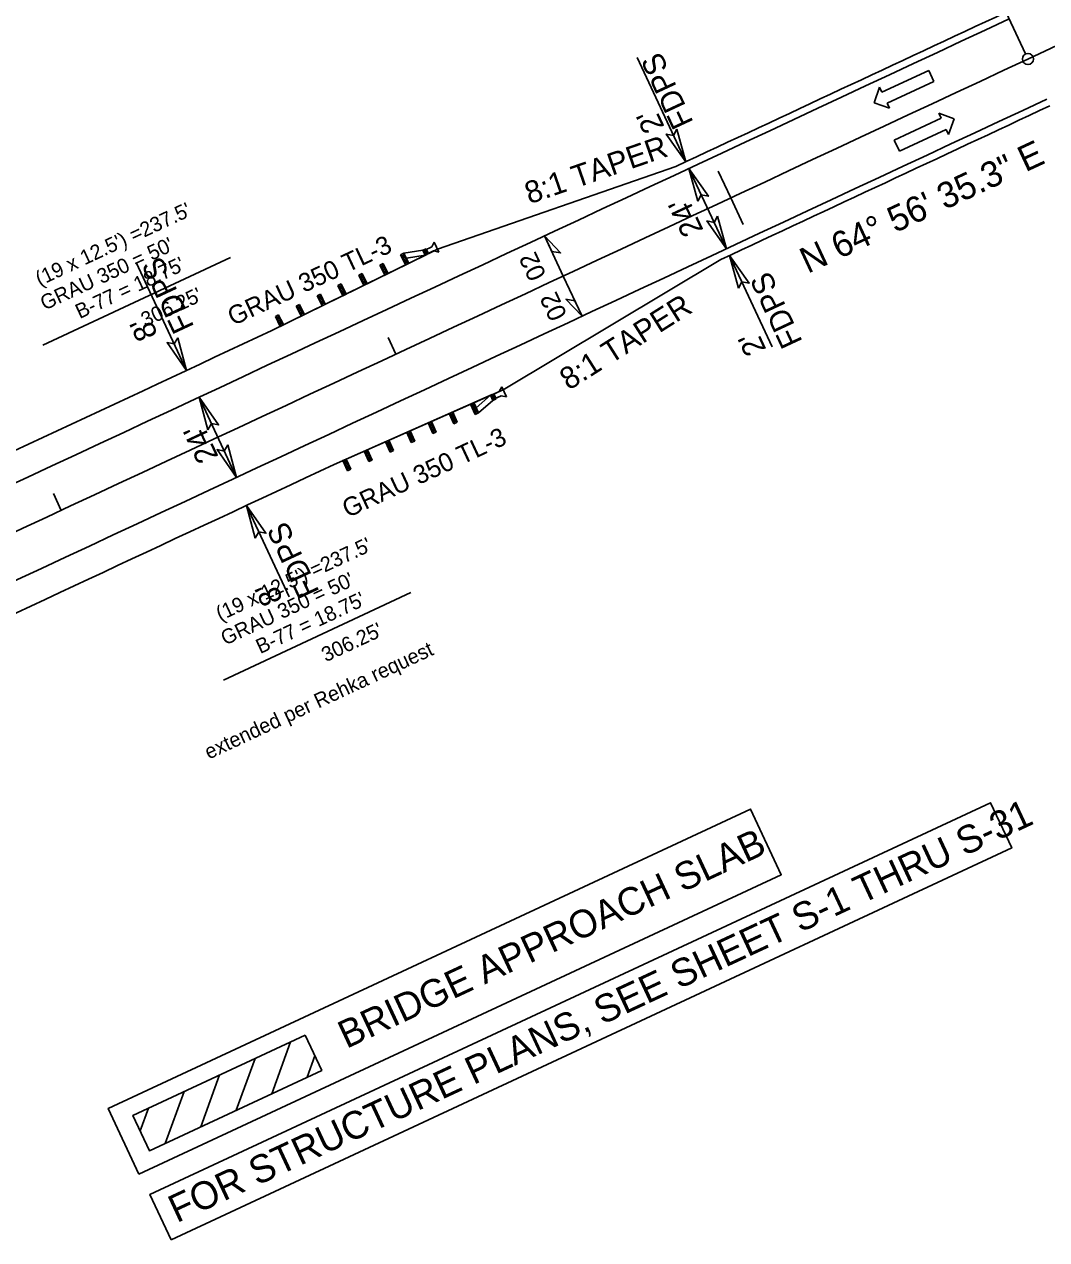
# Model space of a CAD drawing. Extents: x 2320644 to 2322941, y 921672 to 923041.
# Drawn here: x 2321947.4 to 2322224.1, y 922135.5 to 922464.6 of the extents above; entities that cross this region are included whole.
import ezdxf

# ---------------------------------------------------------------- set-up
doc = ezdxf.new("R2010")
doc.units = 0
for name, color, linetype in [('Matchline', 7, 'Continuous'), ('Matchline Text', 7, 'Continuous'), ('Prop Approach Slab', 7, 'Continuous'), ('Prop Conc Shoulder Berm Gutter', 7, 'Continuous'), ('Prop Dimension', 7, 'Continuous'), ('Prop EOT', 7, 'Continuous'), ('Prop Guardrail', 7, 'Continuous'), ('Prop Horizontal Alignment', 7, 'Continuous'), ('Prop Horizontal Alignment Station Label', 7, 'Continuous'), ('Prop Horizontal Alignment Tick Small', 7, 'Continuous'), ('Prop Lane Arrow CELL', 7, 'Continuous'), ('Prop North Arrow NAD83 for Plan Sheets CELL', 7, 'Continuous'), ('Prop Superelevation  Arrow CELL', 7, 'Continuous'), ('Sheet Sticker Exception Certification CELL', 7, 'Continuous'), ('Skimmer Basin Both CELL', 7, 'Continuous')]:
    doc.layers.add(name, color=color, linetype=linetype)

msp = doc.modelspace()

# ---------------------------------------------------------------- linework, layer by layer
at = {"layer": 'Matchline'}
msp.add_line((2322219.06, 922455.24), (2322939.2, 922791.92), dxfattribs=at)
msp.add_arc((2152812.15, 1284810.45), 400000, 294.9912984, 295.0568478, dxfattribs=at)
at = {"layer": 'Prop Approach Slab'}
for radius in [399988, 400012]:
    msp.add_arc((2152812.15, 1284810.45), radius, 294.9912984, 295.0568478, dxfattribs=at)
at = {"layer": 'Prop Conc Shoulder Berm Gutter'}
for p, q in [((2322059.26, 922403.79), (2322123.77, 922426.16)), ((2322014.38, 922381.69), (2322059.26, 922403.79)), ((2322077.05, 922365.66), (2322135.96, 922400.95)), ((2322031.3, 922345.45), (2322077.05, 922365.66))]:
    msp.add_line(p, q, dxfattribs=at)
for radius, start, end in [(399986, 295.0427173, 295.0568478), (400014, 295.0427718, 295.0568478), (399980, 295.0062299, 295.0258255), (400020, 295.0060363, 295.0258255)]:
    msp.add_arc((2152812.15, 1284810.45), radius, start, end, dxfattribs=at)
at = {"layer": 'Prop Dimension'}
msp.add_line((2322218.43, 922456.6), (2322137.68, 922629.33), dxfattribs=at)
msp.add_circle((2322219.06, 922455.24), 1.5, dxfattribs=at)
at = {"layer": 'Prop EOT'}
for p, q in [((2322057.67, 922404.37), (2322055.82, 922403.5)), ((2322058.38, 922405.64), (2322057.67, 922404.37)), ((2322059.62, 922402.98), (2322058.38, 922405.64)), ((2322014.38, 922381.69), (2322056.34, 922402.31)), ((2322049.25, 922402.24), (2322050.14, 922402.68)), ((2322050.6, 922399.49), (2322049.25, 922402.24)), ((2322050.82, 922401.3), (2322049.25, 922402.24)), ((2322050.14, 922402.68), (2322049.92, 922400.86)), ((2322049.92, 922400.86), (2322050.82, 922401.3)), ((2322049.92, 922400.86), (2322051.5, 922399.93)), ((2322050.14, 922402.68), (2322055.23, 922403.44)), ((2322051.5, 922399.93), (2322050.14, 922402.68)), ((2322050.6, 922399.49), (2322050.82, 922401.3)), ((2322050.82, 922401.3), (2322055.89, 922402.09)), ((2322055.23, 922403.44), (2322056.13, 922403.88)), ((2322055.23, 922403.44), (2322055.68, 922403.66)), ((2322055.89, 922402.09), (2322055.23, 922403.44)), ((2322056.79, 922402.53), (2322055.23, 922403.44)), ((2322055.82, 922403.5), (2322056.08, 922402.94)), ((2322056.13, 922403.88), (2322055.89, 922402.09)), ((2322056.08, 922402.94), (2322056.34, 922402.39)), ((2322056.79, 922402.53), (2322056.13, 922403.88)), ((2322056.34, 922402.39), (2322058.19, 922403.26)), ((2322058.19, 922403.26), (2322059.62, 922402.98)), ((2322043.62, 922399.4), (2322044.52, 922399.84)), ((2322044.94, 922396.71), (2322043.62, 922399.4)), ((2322045.18, 922398.5), (2322043.62, 922399.4)), ((2322044.52, 922399.84), (2322044.28, 922398.06)), ((2322044.28, 922398.06), (2322045.18, 922398.5)), ((2322044.28, 922398.06), (2322045.84, 922397.15)), ((2322045.84, 922397.15), (2322044.52, 922399.84)), ((2322044.94, 922396.71), (2322045.18, 922398.5)), ((2322032.29, 922393.88), (2322033.19, 922394.32)), ((2322033.19, 922394.32), (2322032.96, 922392.51)), ((2322034.53, 922391.59), (2322033.19, 922394.32)), ((2322037.9, 922396.75), (2322038.8, 922397.19)), ((2322039.29, 922393.93), (2322037.9, 922396.75)), ((2322039.49, 922395.78), (2322037.9, 922396.75)), ((2322038.8, 922397.19), (2322038.59, 922395.34)), ((2322038.59, 922395.34), (2322039.49, 922395.78)), ((2322038.59, 922395.34), (2322040.18, 922394.37)), ((2322040.18, 922394.37), (2322038.8, 922397.19)), ((2322039.29, 922393.93), (2322039.49, 922395.78)), ((2322026.63, 922391.11), (2322027.53, 922391.55)), ((2322027.98, 922388.37), (2322026.63, 922391.11)), ((2322028.2, 922390.18), (2322026.63, 922391.11)), ((2322027.53, 922391.55), (2322027.3, 922389.74)), ((2322028.87, 922388.81), (2322027.53, 922391.55)), ((2322033.63, 922391.15), (2322032.29, 922393.88)), ((2322033.86, 922392.96), (2322032.29, 922393.88)), ((2322032.96, 922392.51), (2322033.86, 922392.96)), ((2322032.96, 922392.51), (2322034.53, 922391.59)), ((2322033.63, 922391.15), (2322033.86, 922392.96)), ((2322033.63, 922391.15), (2322034.53, 922391.59)), ((2322020.97, 922388.33), (2322021.87, 922388.78)), ((2322022.32, 922385.59), (2322020.97, 922388.33)), ((2322022.54, 922387.41), (2322020.97, 922388.33)), ((2322021.87, 922388.78), (2322021.65, 922386.96)), ((2322023.22, 922386.04), (2322021.87, 922388.78)), ((2322027.3, 922389.74), (2322028.2, 922390.18)), ((2322027.3, 922389.74), (2322028.87, 922388.81)), ((2322027.98, 922388.37), (2322028.2, 922390.18)), ((2322015.34, 922385.51), (2322016.24, 922385.95)), ((2322016.66, 922382.82), (2322015.34, 922385.51)), ((2322016.9, 922384.6), (2322015.34, 922385.51)), ((2322016.24, 922385.95), (2322016, 922384.16)), ((2322016, 922384.16), (2322016.9, 922384.6)), ((2322017.56, 922383.26), (2322016.24, 922385.95)), ((2322016.9, 922384.6), (2322016.66, 922382.82)), ((2322017.56, 922383.26), (2322016.9, 922384.6)), ((2322021.65, 922386.96), (2322022.54, 922387.41)), ((2322021.65, 922386.96), (2322023.22, 922386.04)), ((2322022.32, 922385.59), (2322022.54, 922387.41)), ((2322016, 922384.16), (2322017.56, 922383.26)), ((2322016.66, 922382.82), (2322017.56, 922383.26)), ((2322074.11, 922364.32), (2322075.97, 922365.18)), ((2322074.51, 922364.58), (2322074.2, 922362.8)), ((2322074.51, 922364.58), (2322075.12, 922363.21)), ((2322075.97, 922365.18), (2322076.67, 922366.46)), ((2322076.67, 922366.46), (2322077.91, 922363.79)), ((2322031.3, 922345.45), (2322074.05, 922364.38)), ((2322068.2, 922361.78), (2322069.44, 922358.98)), ((2322068.2, 922361.78), (2322069.73, 922360.79)), ((2322068.82, 922360.38), (2322069.11, 922362.19)), ((2322069.11, 922362.19), (2322070.35, 922359.39)), ((2322069.73, 922360.79), (2322073.6, 922364.17)), ((2322070.35, 922359.39), (2322074.2, 922362.8)), ((2322073.6, 922364.17), (2322074.2, 922362.8)), ((2322075.12, 922363.21), (2322073.6, 922364.17)), ((2322074.37, 922363.77), (2322074.11, 922364.32)), ((2322074.2, 922362.8), (2322075.12, 922363.21)), ((2322074.2, 922362.8), (2322074.66, 922363)), ((2322074.63, 922363.21), (2322074.37, 922363.77)), ((2322076.48, 922364.07), (2322074.63, 922363.21)), ((2322077.91, 922363.79), (2322076.48, 922364.07)), ((2322062.44, 922359.23), (2322063.65, 922356.49)), ((2322062.44, 922359.23), (2322063.96, 922358.27)), ((2322063.04, 922357.86), (2322063.35, 922359.64)), ((2322063.04, 922357.86), (2322063.96, 922358.27)), ((2322064.57, 922356.9), (2322063.04, 922357.86)), ((2322063.35, 922359.64), (2322064.57, 922356.9)), ((2322063.96, 922358.27), (2322063.65, 922356.49)), ((2322068.82, 922360.38), (2322069.73, 922360.79)), ((2322070.35, 922359.39), (2322068.82, 922360.38)), ((2322069.73, 922360.79), (2322069.44, 922358.98)), ((2322069.44, 922358.98), (2322070.35, 922359.39)), ((2322056.68, 922356.68), (2322057.95, 922353.81)), ((2322056.68, 922356.68), (2322058.22, 922355.65)), ((2322057.31, 922355.25), (2322057.59, 922357.09)), ((2322057.31, 922355.25), (2322058.22, 922355.65)), ((2322058.86, 922354.22), (2322057.31, 922355.25)), ((2322057.59, 922357.09), (2322058.86, 922354.22)), ((2322058.22, 922355.65), (2322057.95, 922353.81)), ((2322063.65, 922356.49), (2322064.57, 922356.9)), ((2322045.15, 922351.58), (2322046.39, 922348.79)), ((2322045.15, 922351.58), (2322046.68, 922350.59)), ((2322045.77, 922350.19), (2322046.07, 922351.99)), ((2322046.07, 922351.99), (2322047.3, 922349.2)), ((2322050.91, 922354.13), (2322051.83, 922354.54)), ((2322050.91, 922354.13), (2322052.14, 922351.36)), ((2322050.91, 922354.13), (2322052.44, 922353.15)), ((2322051.53, 922352.74), (2322051.83, 922354.54)), ((2322051.53, 922352.74), (2322052.44, 922353.15)), ((2322053.06, 922351.76), (2322051.53, 922352.74)), ((2322051.83, 922354.54), (2322053.06, 922351.76)), ((2322052.44, 922353.15), (2322052.14, 922351.36)), ((2322052.14, 922351.36), (2322053.06, 922351.76)), ((2322057.95, 922353.81), (2322058.86, 922354.22)), ((2322039.39, 922349.03), (2322040.63, 922346.24)), ((2322039.39, 922349.03), (2322040.92, 922348.04)), ((2322040.01, 922347.63), (2322040.3, 922349.44)), ((2322040.01, 922347.63), (2322040.92, 922348.04)), ((2322040.3, 922349.44), (2322041.54, 922346.64)), ((2322040.92, 922348.04), (2322040.63, 922346.24)), ((2322045.77, 922350.19), (2322046.68, 922350.59)), ((2322047.3, 922349.2), (2322045.77, 922350.19)), ((2322046.68, 922350.59), (2322046.39, 922348.79)), ((2322046.39, 922348.79), (2322047.3, 922349.2)), ((2322033.63, 922346.48), (2322034.54, 922346.88)), ((2322033.63, 922346.48), (2322034.84, 922343.74)), ((2322035.15, 922345.51), (2322033.63, 922346.48)), ((2322034.24, 922345.11), (2322034.54, 922346.88)), ((2322034.24, 922345.11), (2322035.15, 922345.51)), ((2322035.76, 922344.14), (2322034.24, 922345.11)), ((2322034.54, 922346.88), (2322035.76, 922344.14)), ((2322034.54, 922346.88), (2322035.15, 922345.51)), ((2322035.15, 922345.51), (2322034.84, 922343.74)), ((2322041.54, 922346.64), (2322040.01, 922347.63)), ((2322040.63, 922346.24), (2322041.54, 922346.64)), ((2322034.84, 922343.74), (2322035.76, 922344.14))]:
    msp.add_line(p, q, dxfattribs=at)
at = {"layer": 'Prop Guardrail'}
for radius, start in [(399980, 295.0062299), (400020, 295.0060363)]:
    msp.add_arc((2152812.15, 1284810.45), radius, start, 295.0258255, dxfattribs=at)
at = {"layer": 'Prop Horizontal Alignment'}
for q in [(2322135.22, 922424.89), (2322141.99, 922410.39)]:
    msp.add_line((2322138.6, 922417.64), q, dxfattribs=at)
at = {"layer": 'Prop Horizontal Alignment Station Label'}
msp.add_line((2322088.21, 922407.34), (2322093.28, 922396.47), dxfattribs=at)
for points in [[(2322088.21, 922407.34), (2322092.56, 922402.75), (2322090.17, 922403.15)], [(2322098.36, 922385.6), (2322094.01, 922390.19), (2322096.41, 922389.79)]]:
    msp.add_lwpolyline(points, close=True, dxfattribs=at)
at = {"layer": 'Prop Horizontal Alignment Tick Small'}
for p, q in [((2322048, 922375.32), (2322045.88, 922379.85)), ((2321957.38, 922333.02), (2321955.27, 922337.55))]:
    msp.add_line(p, q, dxfattribs=at)
at = {"layer": 'Prop Lane Arrow CELL'}
for p, q in [((2322179.56, 922446.25), (2322192.25, 922452.16)), ((2322192.25, 922452.16), (2322193.64, 922449.17)), ((2322177.42, 922443.38), (2322178.93, 922447.61)), ((2322178.93, 922447.61), (2322179.56, 922446.25)), ((2322193.64, 922449.17), (2322180.95, 922443.26)), ((2322181.59, 922441.9), (2322177.42, 922443.38)), ((2322180.95, 922443.26), (2322181.59, 922441.9)), ((2322195.58, 922439.18), (2322194.95, 922440.54)), ((2322194.95, 922440.54), (2322199.11, 922439.06)), ((2322182.89, 922433.26), (2322195.58, 922439.18)), ((2322199.11, 922439.06), (2322197.61, 922434.83)), ((2322196.97, 922436.19), (2322184.29, 922430.27)), ((2322197.61, 922434.83), (2322196.97, 922436.19)), ((2322184.29, 922430.27), (2322182.89, 922433.26))]:
    msp.add_line(p, q, dxfattribs=at)
at = {"layer": 'Prop North Arrow NAD83 for Plan Sheets CELL'}
for p, q in [((2322126.44, 922427.41), (2322113.28, 922455.61)), ((2322135.56, 922407.88), (2322127.29, 922425.6)), ((2322137.45, 922403.85), (2322130.19, 922419.41)), ((2322149.83, 922377.33), (2322138.3, 922402.04)), ((2321991.32, 922370.93), (2321977.69, 922400.14)), ((2322004.86, 922341.93), (2321994.71, 922363.68)), ((2322019.05, 922309.61), (2322007.51, 922334.32)), ((2322014.36, 922175.06), (2322019.47, 922189.09)), ((2322004.75, 922170.58), (2322009.86, 922184.61)), ((2322023.97, 922179.54), (2322026.07, 922185.29)), ((2321995.13, 922166.1), (2322000.24, 922180.13)), ((2321985.52, 922161.61), (2321990.63, 922175.64)), ((2321978.76, 922164.96), (2321981.02, 922171.16))]:
    msp.add_line(p, q, dxfattribs=at)
for points in [[(2321987.1, 922135.52), (2322214.68, 922241.6), (2322208.98, 922253.83), (2321981.4, 922147.76)], [(2321978.41, 922153.31), (2322152.29, 922234.36), (2322144.01, 922252.13), (2321970.13, 922171.08)], [(2322023.44, 922190.94), (2321976.78, 922169.19), (2321981.24, 922159.62), (2322027.9, 922181.37)]]:
    msp.add_lwpolyline(points, close=True, dxfattribs=at)
at = {"layer": 'Prop Superelevation  Arrow CELL'}
msp.add_line((2322098.36, 922385.6), (2322093.28, 922396.47), dxfattribs=at)
at = {"layer": 'Sheet Sticker Exception Certification CELL'}
for points in [[(2322124.04, 922436.22), (2322126.44, 922427.41), (2322121.17, 922434.93), (2322123.1, 922434.57)], [(2322129.69, 922416.79), (2322127.29, 922425.6), (2322132.57, 922418.07), (2322130.63, 922418.44)], [(2322135.05, 922412.67), (2322137.45, 922403.85), (2322132.17, 922411.38), (2322134.11, 922411.01)], [(2322140.7, 922393.23), (2322138.3, 922402.04), (2322143.57, 922394.52), (2322141.64, 922394.88)], [(2321988.92, 922379.74), (2321991.32, 922370.93), (2321986.05, 922378.45), (2321987.98, 922378.09)], [(2321997.11, 922354.87), (2321994.71, 922363.68), (2321999.98, 922356.16), (2321998.05, 922356.52)], [(2322002.46, 922350.74), (2322004.86, 922341.93), (2321999.58, 922349.46), (2322001.52, 922349.09)], [(2322009.91, 922325.51), (2322007.51, 922334.32), (2322012.79, 922326.8), (2322010.85, 922327.17)]]:
    msp.add_lwpolyline(points, close=True, dxfattribs=at)
at = {"layer": 'Skimmer Basin Both CELL'}
for p, q in [((2321952.42, 922377.79), (2322003.2, 922401.49)), ((2322001.29, 922287.07), (2322052.06, 922310.77))]:
    msp.add_line(p, q, dxfattribs=at)

# ---------------------------------------------------------------- texts
at = {"layer": 'Matchline Text'}
msp.add_text('N 64%%d 56\' 35.3" E', height=7, rotation=24.9913, dxfattribs=at).set_placement((2322159.45, 922397.04))
at = {"layer": 'Prop EOT'}
for rotation, p in [(25.0187, (2322003.91, 922382.91)), (24.9913, (2322034.93, 922330.91))]:
    msp.add_text('GRAU 350 TL-3', height=5, rotation=rotation, dxfattribs=at).set_placement(p)
at = {"layer": 'Prop North Arrow NAD83 for Plan Sheets CELL'}
for s, height, rotation, p in [('FDPS', 6, 115.0187, (2322128.62, 922438.08)), (" 2'", 6, 115.0187, (2322121.73, 922434.86)), ('8:1 TAPER', 6, 19.1276, (2322084.14, 922415.88)), ("24'", 6, 115.0187, (2322131.33, 922408.87)), ('FDPS', 6, 115.0187, (2321993.46, 922382.73)), ('FDPS', 6, 115.0187, (2322158.14, 922378.71)), ('8:1 TAPER', 6, 32.3586, (2322094.78, 922365.38)), (" 8'", 6, 115.0187, (2321984.6, 922378.6)), (" 2'", 6, 115.0187, (2322149.28, 922374.57)), ("24'", 6, 115.0187, (2322000.05, 922347.53)), ('FDPS', 6, 115.0187, (2322027.36, 922310.99)), (" 8'", 6, 115.0187, (2322018.49, 922306.86)), ('FOR STRUCTURE PLANS, SEE SHEET S-1 THRU S-31', 7.5, 24.9913, (2321988.68, 922139.96)), ('BRIDGE APPROACH SLAB', 7.5, 24.9913, (2322034.6, 922187.15))]:
    msp.add_text(s, height=height, rotation=rotation, dxfattribs=at).set_placement(p)
at = {"layer": 'Prop Superelevation  Arrow CELL'}
for p in [(2322088.79, 922396.72), (2322094.43, 922385.89)]:
    msp.add_text('02', height=5, rotation=115.0187, dxfattribs=at).set_placement(p)
at = {"layer": 'Skimmer Basin Both CELL'}
for s, p in [("(19 x 12.5') =237.5'", (2321951.55, 922393.69)), ("GRAU 350 = 50'", (2321952.88, 922387.1)), ("B-77 = 18.75'", (2321962.37, 922384.8)), ("306.25'", (2321980.13, 922382.58)), ("(19 x 12.5') =237.5'", (2322000.42, 922302.97)), ("GRAU 350 = 50'", (2322001.75, 922296.38)), ("B-77 = 18.75'", (2322011.24, 922294.07)), ("306.25'", (2322028.99, 922291.86)), ('extended per Rehka request', (2321997.34, 922265.51))]:
    msp.add_text(s, height=4, rotation=24.9913, dxfattribs=at).set_placement(p)

doc.saveas('drawing.dxf')
